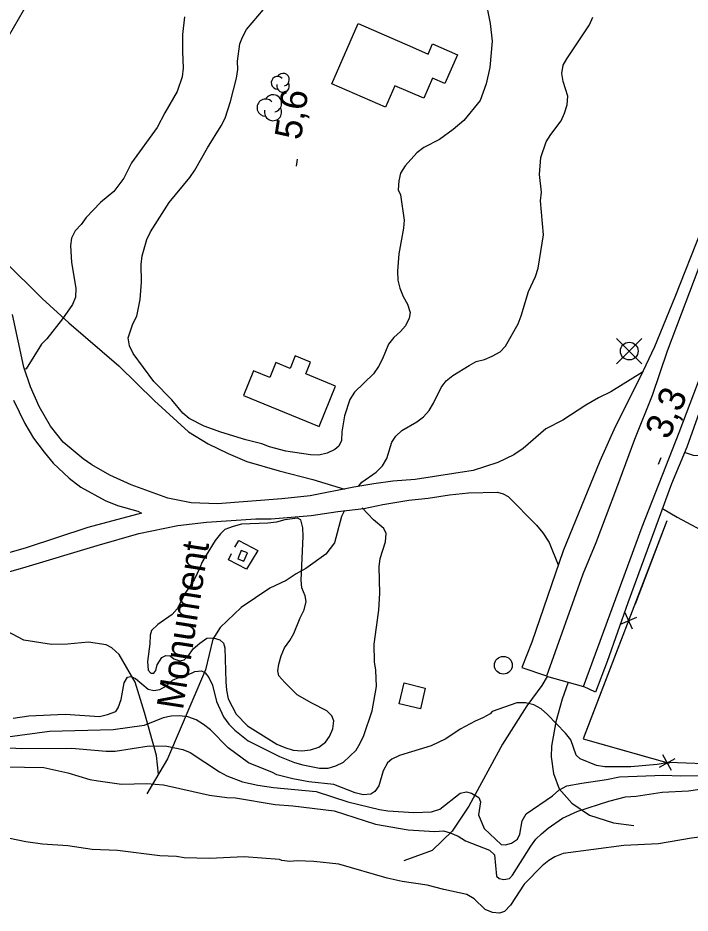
# Model space of a CAD drawing. Extents: x 282461 to 284471, y 5554090 to 5557646.
# Drawn here: x 283275.7 to 283351.1, y 5554604.9 to 5554705.3 of the extents above; entities that cross this region are included whole.
import ezdxf

# ---------------------------------------------------------------- set-up
doc = ezdxf.new("R2010")
doc.units = 0
for name, color, linetype in [('Niveau 1', 7, 'Continuous'), ('Niveau 19', 7, 'Continuous'), ('Niveau 2', 7, 'Continuous'), ('Niveau 21', 7, 'Continuous'), ('Niveau 22', 7, 'Continuous'), ('Niveau 3', 7, 'Continuous'), ('Niveau 31', 7, 'Continuous'), ('Niveau 36', 7, 'Continuous'), ('Niveau 37', 7, 'Continuous'), ('Niveau 39', 7, 'Continuous'), ('Niveau 4', 7, 'Continuous'), ('Niveau 44', 7, 'Continuous')]:
    doc.layers.add(name, color=color, linetype=linetype)

msp = doc.modelspace()

# ---------------------------------------------------------------- linework, layer by layer
at = {"layer": 'Niveau 1'}
for points in [[(283328.09, 5554707.57), (283328.65, 5554704.69), (283328.86, 5554702.72), (283328.62, 5554699.76), (283328.18, 5554697.9), (283327.52, 5554696.04), (283325.7, 5554693.81), (283324.5, 5554692.8), (283322.95, 5554691.68), (283321.22, 5554690.78), (283320.42, 5554690.19), (283319.11, 5554688.72), (283318.6, 5554687.9), (283318.38, 5554687.03), (283318.34, 5554686.04), (283318.58, 5554685.47), (283318.98, 5554682.64), (283318.93, 5554681.71)], [(283318.93, 5554681.71), (283318.4, 5554678.86), (283318.25, 5554676.89), (283318.27, 5554675.91), (283318.52, 5554674.98), (283318.88, 5554674.06), (283319.36, 5554673.2), (283319.66, 5554672.28), (283319.56, 5554671.64), (283319.16, 5554670.76), (283318.59, 5554670.12), (283317.85, 5554669.47), (283317.23, 5554668.71), (283316.56, 5554667.07), (283316.11, 5554666.2), (283315.54, 5554665.38), (283313.43, 5554663.32), (283312.92, 5554662.5), (283312.31, 5554660.69), (283311.99, 5554658.89), (283311.95, 5554657.91), (283311.67, 5554657.27), (283311.21, 5554656.91), (283310.35, 5554656.49), (283309.42, 5554656.25), (283308.5, 5554656.29), (283305.71, 5554656.71), (283303.9, 5554657.2), (283303.03, 5554657.54), (283301.23, 5554657.97), (283298.43, 5554658.86), (283296.57, 5554659.52), (283294.87, 5554660.36), (283294.17, 5554660.99), (283292.93, 5554662.48), (283290.92, 5554664.53), (283288.61, 5554667.68), (283288.19, 5554668.54), (283288.06, 5554669.41), (283288.56, 5554670.98), (283289.01, 5554671.85), (283289.39, 5554673.71), (283289.53, 5554675.68), (283289.5, 5554677.65), (283289.6, 5554678.64), (283290.15, 5554680.44), (283290.54, 5554681.32), (283292.63, 5554684.59), (283294.96, 5554687.41), (283295.53, 5554688.23), (283296.94, 5554690.74), (283298.47, 5554693.2), (283298.92, 5554694.08), (283299.52, 5554695.94), (283300.18, 5554698.56), (283300.34, 5554699.54), (283300.32, 5554700.47), (283300.58, 5554702.39), (283300.86, 5554703.14), (283301.31, 5554704.02), (283303.87, 5554707.02)], [(283295.45, 5554642.3), (283294.43, 5554640.78), (283293.53, 5554639.03), (283292.96, 5554638.38), (283291.36, 5554637.26), (283290.67, 5554636.61), (283290.5, 5554636.09), (283290.46, 5554635.1), (283290.2, 5554633.13), (283290.28, 5554632.15), (283290.57, 5554631.8), (283290.92, 5554631.81), (283291.15, 5554632.1), (283291.31, 5554632.74), (283291.82, 5554633.56), (283292.28, 5554633.8), (283292.74, 5554633.75), (283293.15, 5554633.41), (283293.85, 5554633.19), (283294.32, 5554633.31), (283294.77, 5554633.72), (283295.34, 5554634.54), (283296.08, 5554635.19), (283296.88, 5554635.72), (283297.58, 5554635.79), (283298.34, 5554635.57), (283298.75, 5554635.17), (283298.87, 5554634.65), (283298.99, 5554630.83), (283299.06, 5554629.91), (283299.25, 5554628.93), (283300.15, 5554627.2), (283301.44, 5554625.89), (283304.72, 5554623.86), (283305.6, 5554623.47), (283306.53, 5554623.19), (283307.52, 5554623.09), (283308.5, 5554623.22), (283309.42, 5554623.53), (283310.17, 5554624.06), (283310.62, 5554624.7), (283311.01, 5554625.58), (283311.11, 5554626.45), (283310.87, 5554627.02), (283310.34, 5554627.6), (283308.65, 5554628.44), (283307.01, 5554629.4), (283305.6, 5554630.76), (283304.95, 5554631.51), (283304.82, 5554632.08), (283304.93, 5554632.84), (283305.2, 5554633.77), (283305.59, 5554634.64), (283306.16, 5554635.46), (283306.61, 5554636.28), (283307.34, 5554638.03), (283307.79, 5554638.91), (283308, 5554639.84), (283307.88, 5554640.47), (283307.52, 5554641.39), (283307.44, 5554642.26), (283307.66, 5554647.13), (283307.64, 5554648.11), (283307.39, 5554649.03), (283307.04, 5554649.2), (283305.6, 5554649.01), (283304.68, 5554648.76), (283303.69, 5554648.63), (283300.74, 5554648.52), (283299.81, 5554648.28), (283298.89, 5554647.92), (283298.38, 5554647.45), (283297.81, 5554646.68), (283296.79, 5554645.05), (283296.29, 5554644.23), (283296.12, 5554643.7), (283295.45, 5554642.3)]]:
    msp.add_lwpolyline(points, dxfattribs=at)
at = {"layer": 'Niveau 19'}
for points in [[(283345.73, 5554665.58), (283342.16, 5554663.36), (283340.78, 5554662.7), (283339.37, 5554661.86), (283336.78, 5554660.2), (283334.88, 5554659.21), (283332.33, 5554657), (283331.29, 5554656.32), (283329.5, 5554655.45), (283326.73, 5554654.54), (283320.23, 5554653.52), (283317.71, 5554653.34), (283315.61, 5554653.06), (283313.35, 5554652.68), (283308.47, 5554651.69), (283305.27, 5554651.35), (283298.07, 5554650.8), (283295.09, 5554650.92), (283292.5, 5554651.46), (283288.39, 5554652.95), (283285.99, 5554654.02), (283283.97, 5554655.18), (283282.98, 5554655.86), (283280.76, 5554657.74), (283279.32, 5554659.53), (283278.05, 5554661.73), (283277.09, 5554663.94), (283276.35, 5554666.12), (283275.08, 5554672.04)], [(283275.18, 5554662.42), (283276.46, 5554659.8), (283277.43, 5554658.17), (283278.61, 5554656.61), (283279.64, 5554655.35), (283281.43, 5554653.68), (283282.74, 5554652.69), (283285.46, 5554651.18), (283286.86, 5554650.62), (283289.13, 5554649.99), (283289.54, 5554649.76), (283283.53, 5554648.14), (283276.62, 5554645.88), (283274.39, 5554645.24)], [(283347.98, 5554650.27), (283349.6, 5554649.32), (283355.39, 5554646.22), (283358.66, 5554652.36), (283368, 5554648.23), (283370.4, 5554654.53), (283366.9, 5554655.46), (283363.52, 5554656.05), (283359.63, 5554656.57), (283353.19, 5554656.12), (283351.45, 5554656.21), (283350.43, 5554656.56)], [(283272.76, 5554642.67), (283276.22, 5554643.61), (283284.55, 5554646.15), (283289.23, 5554647.49), (283293.63, 5554648.36), (283296.83, 5554648.74), (283302.37, 5554649.11), (283304.08, 5554649.13), (283308.56, 5554649.48), (283311.57, 5554649.95), (283314.48, 5554650.3), (283316.61, 5554650.75), (283319.51, 5554651.2), (283321.7, 5554651.45), (283324.08, 5554651.83), (283326.2, 5554652.03), (283329.48, 5554652.13), (283330.09, 5554651.94), (283330.65, 5554651.63), (283333.84, 5554648.4), (283334.55, 5554647.57), (283335.27, 5554646.48), (283336.28, 5554643.95)]]:
    msp.add_lwpolyline(points, dxfattribs=at)
at = {"layer": 'Niveau 2'}
for points in [[(283294.35, 5554705.43), (283294.15, 5554703.46), (283294.12, 5554701.54), (283294.21, 5554699.69), (283294.11, 5554698.7), (283293.55, 5554697.07), (283292.14, 5554694.67), (283291.3, 5554693.03), (283288.4, 5554689.05), (283287.56, 5554687.35), (283286.42, 5554685.83), (283284.94, 5554684.59), (283283.34, 5554682.94), (283282.77, 5554682.12), (283282.09, 5554681.41), (283281.69, 5554680.59), (283281.59, 5554679.78)], [(283313.91, 5554652.77), (283313.92, 5554652.82), (283314.26, 5554653.23), (283315.86, 5554654.35), (283316.55, 5554655.06), (283317.06, 5554655.88), (283317.61, 5554657.74), (283318.06, 5554658.39), (283318.75, 5554659.04), (283320.41, 5554659.99), (283321.16, 5554660.58), (283321.79, 5554661.29), (283322.3, 5554662.11), (283323.14, 5554663.86), (283323.71, 5554664.62), (283324.45, 5554665.21), (283326.29, 5554666.34), (283327.09, 5554666.76), (283328.02, 5554667.01), (283328.88, 5554667.37), (283329.75, 5554667.85), (283330.37, 5554668.49), (283331.78, 5554671.01), (283332.12, 5554671.88), (283332.94, 5554674.62), (283333.73, 5554676.31), (283334.01, 5554677.25), (283334.64, 5554680.97), (283334.29, 5554684.79), (283334.39, 5554685.77), (283334.19, 5554687.74), (283334.33, 5554689.66), (283334.94, 5554691.41), (283335.45, 5554692.23), (283336.59, 5554693.75), (283336.98, 5554694.63), (283337.26, 5554695.56), (283337.36, 5554696.55), (283336.81, 5554698.16), (283336.68, 5554699.09), (283336.84, 5554700.02), (283337.23, 5554700.72), (283339.78, 5554704.53), (283340.17, 5554705.4)], [(283281.59, 5554679.78), (283281.68, 5554677.87), (283282.19, 5554674.98), (283282.15, 5554673.99), (283281.81, 5554673.18), (283280.68, 5554671.54), (283278.92, 5554669.31), (283278.34, 5554668.72), (283276.59, 5554665.96), (283276.51, 5554665.9)], [(283292.35, 5554630.4), (283293.03, 5554631.04), (283293.73, 5554631.34), (283294.65, 5554631.59), (283295.51, 5554632.01), (283296.27, 5554632.08), (283296.67, 5554631.85), (283297.09, 5554631.34), (283297.51, 5554630.48), (283297.94, 5554628.63), (283298.73, 5554626.9), (283299.32, 5554626.1), (283300.02, 5554625.42), (283301.49, 5554624.22), (283305, 5554622.48), (283306.69, 5554621.81), (283307.63, 5554621.54), (283309.49, 5554621.16), (283310.47, 5554621.17), (283311.34, 5554621.42), (283312.2, 5554621.84), (283313.63, 5554623.19), (283314.08, 5554623.95), (283314.47, 5554624.83), (283315.42, 5554627.57), (283315.9, 5554630.3), (283315.81, 5554632.15), (283315.68, 5554633.08), (283315.65, 5554635.05), (283316.17, 5554638.88), (283316.25, 5554640.8), (283316.21, 5554643.75), (283316.31, 5554644.68), (283316.91, 5554646.54), (283316.96, 5554647.47), (283316.72, 5554648.05), (283315.54, 5554649.02), (283314.28, 5554650.35)], [(283275.13, 5554626.77), (283276.92, 5554627.03), (283280.98, 5554627.2), (283284.81, 5554626.97), (283285.73, 5554627.16), (283286.65, 5554627.53), (283286.94, 5554627.94), (283287.27, 5554628.87), (283287.59, 5554630.73), (283287.98, 5554631.37), (283288.33, 5554631.43), (283288.86, 5554631.21), (283290.27, 5554630.02), (283290.91, 5554629.85), (283291.6, 5554629.98), (283292.35, 5554630.4)], [(283354.55, 5554621.58), (283348.69, 5554621.78), (283347.36, 5554621.58), (283344.4, 5554621.3), (283341.5, 5554621.32), (283340.56, 5554621.47), (283338.75, 5554622.2), (283338.28, 5554622.6), (283337.68, 5554624.33), (283337.08, 5554625.07), (283335.08, 5554627.19), (283334.37, 5554627.82), (283333.55, 5554628.27), (283332.62, 5554628.49), (283331.63, 5554628.47), (283328.86, 5554627.5), (283328.63, 5554627.26), (283327.83, 5554626.79), (283326.96, 5554626.42), (283325.29, 5554625.53), (283323.68, 5554624.46), (283322.01, 5554623.68), (283318.49, 5554622.58), (283317.63, 5554622.16), (283317.11, 5554621.75), (283316.66, 5554620.87), (283316.16, 5554619.18), (283315.71, 5554618.54), (283315.25, 5554618.24), (283314.38, 5554618.17), (283313.51, 5554618.38), (283311.11, 5554619.33), (283308.32, 5554619.64), (283306.52, 5554619.96), (283304.71, 5554620.39), (283304.24, 5554620.68), (283301.55, 5554621.74), (283299.26, 5554623.44), (283297.26, 5554625.44), (283296.49, 5554626.07)], [(283296.49, 5554626.07), (283295.67, 5554626.57), (283294.74, 5554626.91), (283293.75, 5554627.01), (283292.88, 5554626.99), (283291.96, 5554626.81), (283289.82, 5554625.96), (283286.35, 5554625.44), (283279.21, 5554625.27), (283274.52, 5554624.62)], [(283268.73, 5554623.78), (283276.11, 5554623.38), (283281.69, 5554623.41), (283285.58, 5554623.06), (283286.57, 5554623.08), (283290.39, 5554623.66), (283292.37, 5554623.63), (283294.18, 5554623.25), (283294.99, 5554622.92), (283298.28, 5554620.76), (283299.1, 5554620.31), (283300.85, 5554619.64), (283302.6, 5554619.26), (283304.35, 5554619), (283309.12, 5554618.55), (283312.68, 5554617.39), (283316.24, 5554616.51), (283317.17, 5554616.36), (283320.08, 5554616.17), (283322.05, 5554616.26), (283322.98, 5554616.56), (283325.27, 5554618.34), (283325.97, 5554618.52), (283326.55, 5554618.36), (283327.37, 5554617.85), (283327.55, 5554617.39), (283327.34, 5554615.93), (283327.95, 5554614.38), (283329.89, 5554612.61), (283330.36, 5554612.56), (283331.05, 5554612.74), (283331.69, 5554613.21), (283331.97, 5554613.74), (283332.23, 5554615.25), (283332.69, 5554616.02), (283335.62, 5554618.04), (283336.36, 5554618.69), (283337.23, 5554619.16), (283338.91, 5554619.48), (283341.69, 5554619.87), (283343.14, 5554620.18), (283348.07, 5554620.38), (283349.99, 5554620.29), (283358.65, 5554620.43)], [(283272.02, 5554621.35), (283278.59, 5554621.22), (283281.27, 5554620.62), (283283.73, 5554619.9), (283284.66, 5554619.74), (283287.28, 5554619.38), (283290.13, 5554619.42), (283291.99, 5554619.28), (283297.18, 5554618.14), (283299.1, 5554617.88), (283300.09, 5554617.83), (283304.52, 5554617.09), (283306.5, 5554616.95), (283311.16, 5554616.38), (283315.78, 5554614.88), (283319.45, 5554614.24), (283322.42, 5554614.06), (283323.4, 5554614.13), (283324.16, 5554613.91), (283325.04, 5554613.52), (283325.86, 5554613.01), (283328.55, 5554611.94), (283329.14, 5554611.43), (283329.35, 5554609.05), (283329.65, 5554608.77), (283330.17, 5554608.66), (283330.81, 5554608.78), (283331.16, 5554609.14), (283333.2, 5554612.42), (283333.77, 5554613.19), (283334.4, 5554613.78), (283335.14, 5554614.43)], [(283335.14, 5554614.43), (283336.75, 5554615.56), (283338.48, 5554616.34), (283341.96, 5554617.44), (283343.81, 5554617.93), (283345.03, 5554618.01), (283347.93, 5554618.46), (283350.89, 5554618.62), (283353.68, 5554619.02)]]:
    msp.add_lwpolyline(points, dxfattribs=at)
at = {"layer": 'Niveau 21'}
for points in [[(283353.32, 5554722.18), (283352.99, 5554721.42), (283361.67, 5554718.54), (283363.27, 5554717.84), (283364.39, 5554717.16), (283365.01, 5554716.3), (283365.06, 5554714.73), (283364.87, 5554713.6), (283363.58, 5554710.19), (283361.66, 5554705.61), (283358.36, 5554698.2), (283354.93, 5554689.88), (283353.51, 5554685.59), (283352.3, 5554681.45), (283349.37, 5554674), (283347.07, 5554668.42), (283345.47, 5554665.03), (283342.66, 5554659.45), (283340.93, 5554655.59), (283336.82, 5554645.52), (283333.3, 5554635.3), (283332.21, 5554632.45), (283334.96, 5554631.51)], [(283372.62, 5554715.06), (283367.79, 5554704.08), (283362.81, 5554691.59), (283361.08, 5554686.92), (283358.33, 5554678.13), (283357.14, 5554674.77), (283353.74, 5554665.35), (283352.27, 5554661.59), (283350.68, 5554657.18), (283348.98, 5554653.04), (283344.08, 5554639.71), (283341.78, 5554633.11), (283340.45, 5554629.69), (283339.12, 5554630.33)], [(283363.33, 5554707.26), (283362.29, 5554704.34), (283360.83, 5554700.81), (283356.57, 5554689.67), (283353.65, 5554681.91), (283352.58, 5554678.7), (283348.51, 5554667.94), (283346.8, 5554662.95), (283344.81, 5554658.04), (283342.82, 5554652.55), (283340.48, 5554646.43), (283339.05, 5554642.92), (283334.95, 5554631.48), (283339.12, 5554630.33), (283345.69, 5554648.23), (283349.84, 5554658.82), (283354.89, 5554672.1), (283359.97, 5554686.22), (283362.57, 5554693.92), (283369.18, 5554710.08)], [(283271.79, 5554698.35), (283277.97, 5554709.09)]]:
    msp.add_lwpolyline(points, dxfattribs=at)
at = {"layer": 'Niveau 22'}
for points in [[(283274.14, 5554678.06), (283278.41, 5554673.84), (283281.38, 5554671.09), (283286.99, 5554666.28), (283290.99, 5554662.35), (283294.81, 5554658.88), (283297.03, 5554657.53), (283299.25, 5554656.46), (283301.35, 5554655.57), (283304.98, 5554654.51), (283308.76, 5554653.53), (283312.32, 5554652.44)], [(283312.32, 5554650.04), (283311.98, 5554649.38), (283311.2, 5554646.44), (283310.22, 5554645.16), (283307.95, 5554643.54), (283306.89, 5554642.97), (283305.78, 5554642.22), (283303.93, 5554641.34), (283300.7, 5554639.17), (283298.35, 5554636.94), (283297.53, 5554635.61), (283296.71, 5554632.17), (283292.47, 5554622.21), (283290.15, 5554618.26)], [(283291.45, 5554620.48), (283291.23, 5554622.56), (283289.87, 5554627.4), (283288.81, 5554630.8), (283287.03, 5554633.91), (283286.21, 5554634.65), (283285.57, 5554634.99), (283283.61, 5554635.28), (283281.24, 5554635.07), (283279.44, 5554635.04), (283276.36, 5554635.51), (283273.14, 5554637.21), (283269.36, 5554640.71), (283268.17, 5554641.68)], [(283335.05, 5554631.45), (283334.43, 5554630.44), (283332.74, 5554628.14), (283330.03, 5554623.85), (283326.24, 5554616.88), (283324.39, 5554614.09), (283322.12, 5554611.93), (283318.96, 5554610.76)], [(283337.38, 5554630.81), (283336.72, 5554628.91), (283336, 5554626.35), (283335.52, 5554623.62), (283335.5, 5554622.44), (283335.75, 5554620.54), (283336.37, 5554618.85), (283337.8, 5554617.23), (283339.77, 5554615.9), (283342.49, 5554615.04), (283344.76, 5554614.72)]]:
    msp.add_lwpolyline(points, dxfattribs=at)
at = {"layer": 'Niveau 3'}
for p, q in [((283306.92, 5554688.69), (283307.04, 5554689.48)), ((283347.51, 5554655.26), (283347.82, 5554656))]:
    msp.add_line(p, q, dxfattribs=at)
at = {"layer": 'Niveau 31'}
for points in [[(283319.92, 5554702.02), (283321.68, 5554701.26), (283322.16, 5554702.39), (283324.97, 5554701.17), (283323.57, 5554697.95), (283322.18, 5554698.55), (283321.2, 5554696.3), (283317.95, 5554697.71), (283316.91, 5554695.31), (283310.89, 5554697.92), (283313.82, 5554704.67), (283319.92, 5554702.02)], [(283309.46, 5554659.48), (283311.31, 5554664.01), (283307.96, 5554665.39), (283308.5, 5554666.7), (283306.79, 5554667.4), (283306.22, 5554666), (283304.61, 5554666.66), (283303.92, 5554664.98), (283302.09, 5554665.73), (283300.96, 5554662.96), (283309.46, 5554659.48)], [(283318.98, 5554630.71), (283321.36, 5554630.14), (283320.81, 5554627.82), (283318.42, 5554628.39), (283318.98, 5554630.71)]]:
    msp.add_lwpolyline(points, dxfattribs=at)
at = {"layer": 'Niveau 36'}
for p, q in [((283345.64, 5554666.52), (283342.82, 5554669.34)), ((283342.82, 5554666.52), (283345.64, 5554669.34))]:
    msp.add_line(p, q, dxfattribs=at)
for centre in [(283344.24, 5554667.94), (283330.12, 5554632.7)]:
    msp.add_circle(centre, 1, dxfattribs=at)
at = {"layer": 'Niveau 37'}
for p, q in [((283343.76, 5554638.62), (283344.58, 5554636.79)), ((283343.25, 5554637.3), (283345.08, 5554638.11)), ((283347.63, 5554621.28), (283349.38, 5554622.25)), ((283348.99, 5554620.89), (283348.02, 5554622.64))]:
    msp.add_line(p, q, dxfattribs=at)
for points in [[(283348.47, 5554648.91), (283339.08, 5554624.45), (283348.7, 5554621.71)], [(283348.47, 5554648.91), (283344.89, 5554639.57)], [(283300.01, 5554645.93), (283300.46, 5554646.69), (283302.57, 5554645.57), (283301.33, 5554643.46), (283299.28, 5554644.53), (283299.62, 5554645.23)], [(283300.01, 5554645.93), (283300.46, 5554646.69), (283302.57, 5554645.57), (283301.33, 5554643.46), (283299.28, 5554644.53), (283299.62, 5554645.23)], [(283343.45, 5554635.84), (283339.87, 5554626.5)], [(283339.87, 5554626.5), (283339.08, 5554624.45), (283346.58, 5554622.31)]]:
    msp.add_lwpolyline(points, dxfattribs=at)
at = {"layer": 'Niveau 39'}
msp.add_lwpolyline([(283301.42, 5554645.31), (283300.72, 5554645.58), (283300.33, 5554644.65), (283301.03, 5554644.37), (283301.42, 5554645.31)], dxfattribs=at)
at = {"layer": 'Niveau 4'}
for points in [[(283421.33, 5554615.11), (283410.97, 5554614.95), (283408, 5554615.19), (283407.06, 5554615.35), (283400.31, 5554615.3), (283397.34, 5554615.37), (283396.35, 5554615.47), (283387.04, 5554615.33), (283382.62, 5554615.43), (283381.04, 5554615.64), (283374.59, 5554615.54), (283367.91, 5554614.92), (283365.23, 5554614.76), (283363.43, 5554614.44), (283356.69, 5554613.81), (283353.85, 5554613.65), (283351.23, 5554613.32), (283347.52, 5554612.68), (283343.62, 5554612.5)], [(283343.62, 5554612.5), (283336.83, 5554611.58), (283335.91, 5554611.22), (283335.22, 5554610.8), (283334.47, 5554610.21), (283332.47, 5554608.14), (283330.93, 5554605.8), (283330.25, 5554605.09), (283329.67, 5554604.9), (283328.91, 5554604.95), (283328.09, 5554605.29), (283326.85, 5554606.49), (283326.03, 5554607), (283323.46, 5554607.54), (283321.59, 5554608.03), (283318.79, 5554608.45), (283317.1, 5554608.83), (283311.66, 5554610.38), (283308.87, 5554610.68), (283307.01, 5554610.77), (283306.19, 5554610.7), (283305.26, 5554610.8), (283305.03, 5554610.91), (283301.07, 5554611.2), (283297.17, 5554611.02), (283294.32, 5554611.1), (283293.45, 5554611.26), (283291.58, 5554611.34), (283286.86, 5554611.91), (283284.01, 5554612.04), (283281.27, 5554612.46), (283278.42, 5554612.65), (283276.56, 5554612.91), (283273.87, 5554613.45)]]:
    msp.add_lwpolyline(points, dxfattribs=at)
at = {"layer": 'Niveau 44'}
for centre, radius, start, end in [((283304.8, 5554698.03), 0.708, 44.1154, 269.804), ((283305.41, 5554698.38), 0.708, 282.2692, 149.7263), ((283305.41, 5554697.67), 0.708, 166.9369, 29.6212), ((283304.29, 5554695.72), 0.968, 282.2692, 149.7263), ((283303.46, 5554695.24), 0.968, 44.1154, 269.804), ((283304.29, 5554694.75), 0.968, 166.9369, 29.6212)]:
    msp.add_arc(centre, radius, start, end, dxfattribs=at)

# ---------------------------------------------------------------- texts
at = {"layer": 'Niveau 3'}
for s, rotation, p in [('5,6  ', 81.0957, (283307.4, 5554691.53)), ('3,3  ', 67.2871, (283348.66, 5554657.9))]:
    msp.add_text(s, height=3, rotation=rotation, dxfattribs=at).set_placement(p)
at = {"layer": 'Niveau 39'}
msp.add_text('Monument', height=3, rotation=81.0598, dxfattribs=at).set_placement((283294.18, 5554627.61))

doc.saveas('drawing.dxf')
